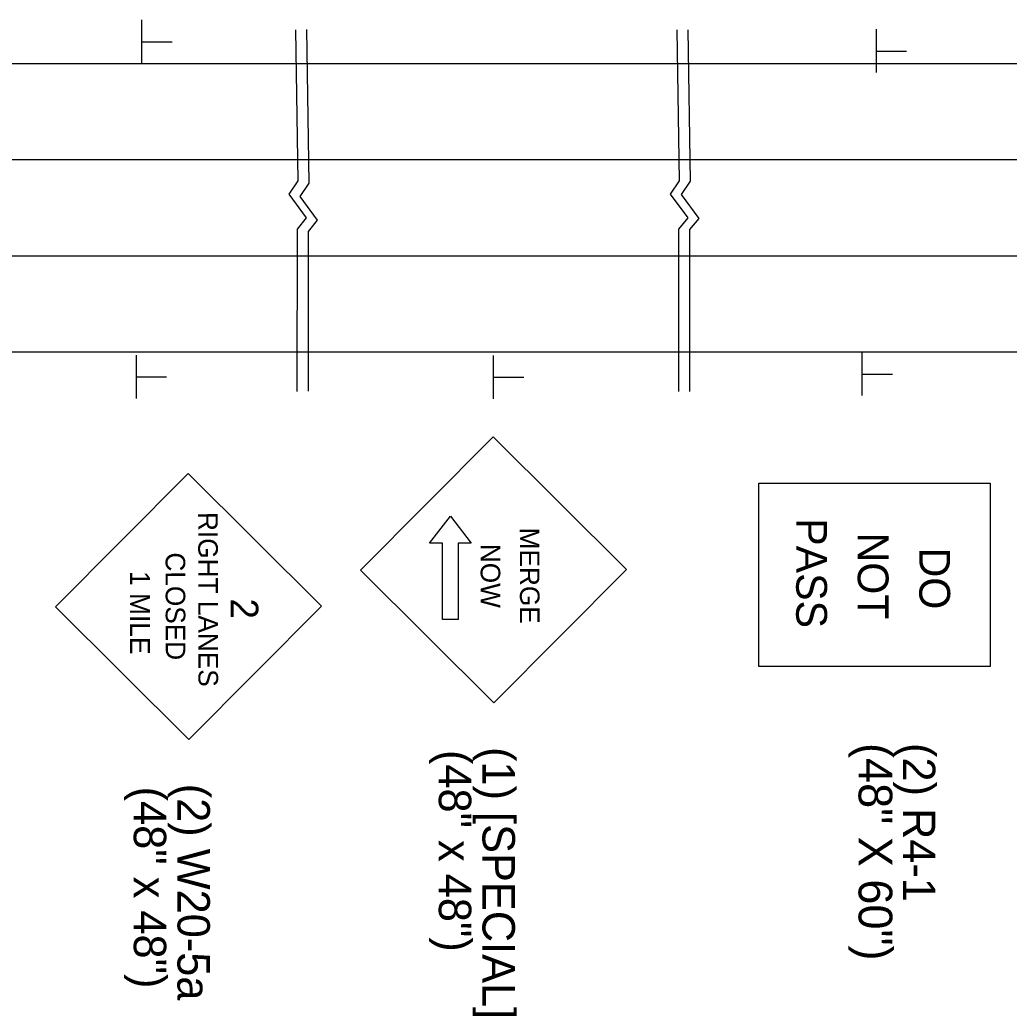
# Model space of a CAD drawing. Extents: x -100 to 745, y -1581 to -107.
# Drawn here: x 205.6 to 223.49, y -523.49 to -505.47 of the extents above; entities that cross this region are included whole.
import ezdxf

# ---------------------------------------------------------------- set-up
doc = ezdxf.new("R2010")
doc.units = 0
doc.layers.add('Default', color=7, linetype='Continuous')

msp = doc.modelspace()

# ---------------------------------------------------------------- linework, layer by layer
at = {"layer": 'Default'}
for p, q in [((207.801, -506.256), (207.801, -505.474)), ((221.089, -506.426), (221.089, -505.643)), ((207.813, -505.867), (208.347, -505.867)), ((221.1, -506.037), (221.634, -506.037)), ((203.422, -506.262), (210.084, -506.262)), ((210.084, -506.262), (216.984, -506.262)), ((216.984, -506.262), (224.378, -506.262)), ((203.966, -508.001), (210.084, -508.001)), ((210.084, -508.001), (216.984, -508.001)), ((216.984, -508.001), (224.424, -508.001)), ((203.966, -509.739), (210.084, -509.739)), ((210.084, -509.739), (216.984, -509.739)), ((216.984, -509.739), (224.424, -509.739)), ((203.427, -511.478), (210.084, -511.478)), ((207.704, -512.321), (207.704, -511.538)), ((210.084, -511.478), (216.984, -511.478)), ((214.164, -512.326), (214.164, -511.544)), ((216.984, -511.478), (224.47, -511.478)), ((220.831, -512.27), (220.831, -511.487)), ((220.842, -511.881), (221.377, -511.881)), ((207.716, -511.931), (208.25, -511.931)), ((214.176, -511.937), (214.71, -511.937)), ((211.757, -515.424), (214.158, -513.014)), ((216.566, -515.416), (214.158, -513.014)), ((206.24, -516.088), (208.642, -513.677)), ((211.05, -516.079), (208.642, -513.677)), ((213.007, -514.939), (213.382, -514.452)), ((213.382, -514.452), (213.757, -514.939)), ((213.242, -514.939), (213.007, -514.939)), ((213.242, -516.318), (213.242, -514.939)), ((213.523, -514.939), (213.523, -516.318)), ((213.757, -514.939), (213.523, -514.939)), ((214.167, -517.826), (211.757, -515.424)), ((214.167, -517.826), (216.566, -515.416)), ((208.65, -518.489), (206.24, -516.088)), ((208.65, -518.489), (211.05, -516.079)), ((213.523, -516.318), (213.242, -516.318))]:
    msp.add_line(p, q, dxfattribs=at)
for points in [[(210.579, -505.651), (210.62, -508.382), (210.458, -508.624), (210.775, -509.056), (210.608, -509.256), (210.607, -512.192)], [(210.779, -505.648), (210.821, -508.424), (210.658, -508.665), (210.975, -509.098), (210.808, -509.298), (210.808, -512.189)], [(217.479, -505.651), (217.521, -508.382), (217.359, -508.624), (217.675, -509.056), (217.508, -509.256), (217.508, -512.193)], [(217.679, -505.651), (217.721, -508.39), (217.558, -508.632), (217.875, -509.065), (217.708, -509.265), (217.708, -512.193)]]:
    msp.add_lwpolyline(points, dxfattribs=at)
msp.add_lwpolyline([(223.145, -517.172), (218.963, -517.172), (218.963, -513.854), (223.145, -513.854)], close=True, dxfattribs=at)

# ---------------------------------------------------------------- texts
for s, height, rotation, p in [('RIGHT LANES', 0.35441, 270.1004, (208.82, -514.375)), ('PASS', 0.5566, 270, (219.637, -514.487)), ('MERGE', 0.3544, 270.1004, (214.638, -514.658)), ('NOT', 0.5566, 270, (220.75, -514.746)), ('CLOSED', 0.3543, 270.1003, (208.231, -515.106)), ('NOW', 0.3543, 270.1003, (213.929, -514.951)), ('DO', 0.5566, 270, (221.864, -515.018)), ('1 MILE', 0.3567, 270.0006, (207.59, -515.442)), ('2', 0.5, 270, (209.408, -515.937)), ('(48" x 48")', 0.5862, 270, (213.173, -518.679)), ('(1) [SPECIAL]', 0.5862, 270, (213.963, -518.626)), ('(48" X 60")', 0.61, 270, (220.765, -518.553)), ('(2) R4-1', 0.5862, 270, (221.567, -518.553)), ('(48" x 48")', 0.5862, 270, (207.656, -519.342)), ('(2) W20-5a', 0.5862, 270, (208.446, -519.289))]:
    msp.add_text(s, height=height, rotation=rotation, dxfattribs=at).set_placement(p)

doc.saveas('drawing.dxf')
